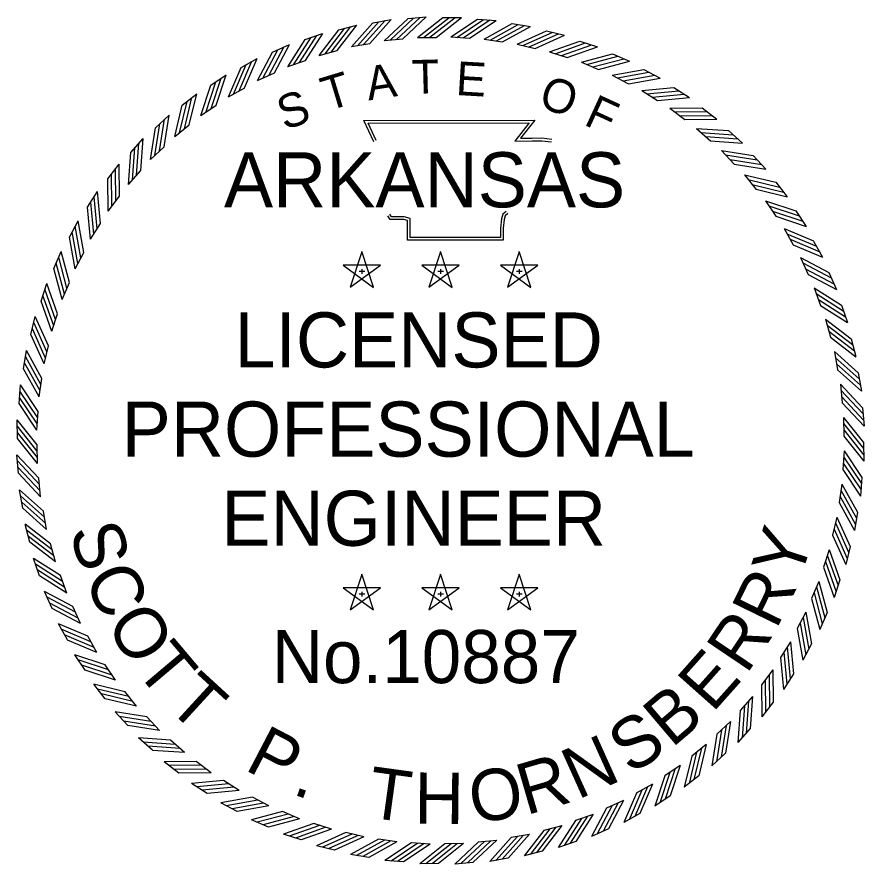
# Model space of a CAD drawing. Extents: x 166 to 3426, y 71 to 2074.
# Drawn here: x 2971.7 to 3220.1, y 237.2 to 485.7 of the extents above; entities that cross this region are included whole.
import ezdxf

# ---------------------------------------------------------------- set-up
doc = ezdxf.new("R2010")
doc.units = 0
doc.layers.add('STAMP', color=7, linetype='Continuous')

msp = doc.modelspace()

# ---------------------------------------------------------------- linework, layer by layer
at = {"layer": 'STAMP'}
for p, q in [((3076.12, 483.94), (3081.47, 484.89)), ((3086.3, 485.16), (3091.72, 485.66)), ((3096.6, 485.46), (3102.04, 485.46)), ((3106.79, 485.05), (3112.22, 484.65)), ((3066.07, 481.89), (3071.33, 483.27)), ((3116.96, 483.73), (3122.34, 482.89)), ((3056.22, 479.01), (3061.35, 480.82)), ((3089.18, 479.67), (3094.63, 479.67)), ((3098.96, 479.82), (3104.4, 479.42)), ((3126.99, 481.58), (3132.28, 480.29)), ((3046.65, 475.33), (3051.61, 477.56)), ((3069.81, 476.95), (3075.18, 477.9)), ((3079.44, 478.71), (3084.87, 479.21)), ((3108.73, 479.17), (3114.12, 478.32)), ((3118.41, 477.71), (3123.71, 476.42)), ((3136.81, 478.6), (3141.97, 476.88)), ((3060.36, 474.4), (3065.63, 475.79)), ((3127.93, 475.45), (3133.11, 473.73)), ((3146.34, 474.82), (3151.34, 472.68)), ((3037.41, 470.87), (3042.17, 473.51)), ((3051.15, 471.08), (3056.29, 472.89)), ((3137.24, 472.42), (3142.25, 470.27)), ((3155.53, 470.27), (3160.34, 467.73)), ((3028.58, 465.67), (3033.1, 468.69)), ((3042.25, 467.01), (3047.23, 469.24)), ((3146.26, 468.63), (3151.08, 466.08)), ((3033.72, 462.21), (3038.49, 464.85)), ((3164.31, 464.98), (3168.9, 462.04)), ((3020.2, 459.75), (3024.46, 463.13)), ((3154.94, 464.1), (3159.53, 461.16)), ((3025.61, 456.73), (3030.15, 459.76)), ((3163.22, 458.88), (3167.55, 455.57)), ((3172.63, 458.97), (3176.95, 455.67)), ((3012.34, 453.16), (3016.31, 456.89)), ((3017.98, 450.6), (3022.25, 453.99)), ((3171.03, 452.99), (3175.08, 449.33)), ((3180.42, 452.31), (3184.46, 448.66)), ((3005.05, 445.95), (3008.7, 449.99)), ((3010.88, 443.86), (3014.86, 447.59)), ((3178.34, 446.47), (3182.07, 442.49)), ((3187.64, 445.02), (3191.36, 441.05)), ((2998.38, 438.16), (3001.68, 442.48)), ((3004.37, 436.56), (3008.02, 440.6)), ((3185.08, 439.38), (3188.47, 435.1)), ((3194.23, 437.16), (3197.61, 432.89)), ((2992.38, 429.84), (2995.31, 434.42)), ((2998.48, 428.74), (3001.79, 433.08)), ((3191.21, 431.75), (3194.23, 427.21)), ((3200.14, 428.78), (3203.16, 424.25)), ((2987.08, 421.06), (2989.63, 425.87)), ((2993.25, 420.47), (2996.19, 425.06)), ((3196.69, 423.64), (3199.33, 418.87)), ((3205.35, 419.94), (3207.98, 415.18)), ((2982.53, 411.87), (2984.67, 416.87)), ((2988.73, 411.79), (2991.28, 416.61)), ((3072.83, 416.81), (3069.42, 406.37)), ((3076.22, 406.38), (3072.83, 416.83)), ((3095.9, 416.81), (3092.5, 406.37)), ((3099.3, 406.38), (3095.91, 416.83)), ((3118.98, 416.81), (3115.58, 406.37)), ((3122.37, 406.38), (3118.99, 416.83)), ((3201.48, 415.1), (3203.72, 410.13)), ((3078.31, 412.83), (3067.33, 412.84)), ((3067.34, 412.83), (3076.22, 406.36)), ((3069.44, 406.38), (3078.33, 412.82)), ((3101.39, 412.83), (3090.41, 412.84)), ((3090.42, 412.83), (3099.3, 406.36)), ((3092.51, 406.38), (3101.41, 412.82)), ((3124.47, 412.83), (3113.49, 412.84)), ((3113.5, 412.83), (3122.38, 406.36)), ((3115.59, 406.38), (3124.48, 412.82)), ((3072.04, 411.07), (3073.68, 411.07)), ((3072.84, 411.66), (3072.84, 410.28)), ((3095.12, 411.07), (3096.76, 411.07)), ((3095.92, 411.66), (3095.92, 410.28)), ((3118.2, 411.07), (3119.83, 411.07)), ((3118.99, 411.66), (3118.99, 410.28)), ((3209.81, 410.71), (3212.04, 405.74)), ((2978.76, 402.33), (2980.48, 407.49)), ((2984.94, 402.76), (2987.08, 407.78)), ((3205.55, 406.2), (3207.37, 401.06)), ((3213.48, 401.13), (3215.3, 396)), ((2975.78, 392.52), (2977.07, 397.8)), ((2981.9, 393.46), (2983.63, 398.63)), ((3208.87, 397), (3210.26, 391.72)), ((3216.36, 391.29), (3217.75, 386.03)), ((2973.62, 382.49), (2974.47, 387.86)), ((2979.65, 383.93), (2980.94, 389.23)), ((3211.42, 387.55), (3212.37, 382.18)), ((3218.41, 381.24), (3219.36, 375.88)), ((2972.3, 372.32), (2972.7, 377.74)), ((2978.19, 374.25), (2979.04, 379.64)), ((3213.18, 377.92), (3213.68, 372.49)), ((3219.63, 371.06), (3220.13, 365.64)), ((2977.53, 364.49), (2977.93, 369.93)), ((3214.14, 368.18), (3214.2, 362.73)), ((2971.83, 362.07), (2971.78, 367.51)), ((3220, 360.81), (3220.05, 355.37)), ((2977.69, 354.7), (2977.64, 360.16)), ((3214.3, 358.39), (3213.9, 352.95)), ((2972.2, 351.82), (2971.7, 357.24)), ((2978.65, 344.96), (2978.15, 350.39)), ((3219.53, 350.56), (3219.13, 345.14)), ((3213.64, 348.63), (3212.79, 343.24)), ((2973.42, 341.64), (2972.47, 347)), ((2980.41, 335.33), (2979.46, 340.71)), ((3218.21, 340.39), (3217.36, 335.02)), ((3212.18, 338.95), (3210.89, 333.65)), ((2975.47, 331.59), (2974.09, 336.85)), ((2982.96, 325.89), (2981.57, 331.16)), ((3209.93, 329.42), (3208.2, 324.25)), ((3216.05, 330.37), (3214.76, 325.08)), ((2978.35, 321.75), (2976.53, 326.88)), ((2986.28, 316.68), (2984.46, 321.82)), ((3072.83, 322.19), (3069.42, 311.75)), ((3076.22, 311.75), (3072.83, 322.2)), ((3095.9, 322.19), (3092.5, 311.75)), ((3099.3, 311.75), (3095.91, 322.2)), ((3118.98, 322.19), (3115.58, 311.75)), ((3122.37, 311.75), (3118.99, 322.2)), ((3213.07, 320.55), (3211.35, 315.39)), ((3078.31, 318.2), (3067.33, 318.21)), ((3067.34, 318.2), (3076.22, 311.74)), ((3069.44, 311.75), (3078.33, 318.2)), ((3101.39, 318.2), (3090.41, 318.21)), ((3090.42, 318.2), (3099.3, 311.74)), ((3092.51, 311.75), (3101.41, 318.2)), ((3124.47, 318.2), (3113.49, 318.21)), ((3113.5, 318.2), (3122.38, 311.74)), ((3115.59, 311.75), (3124.48, 318.2)), ((3206.89, 320.12), (3204.75, 315.1)), ((2982.02, 312.18), (2979.79, 317.14)), ((3072.04, 316.45), (3073.68, 316.45)), ((3072.84, 317.03), (3072.84, 315.66)), ((3095.12, 316.45), (3096.76, 316.45)), ((3095.92, 317.03), (3095.92, 315.66)), ((3118.2, 316.45), (3119.83, 316.45)), ((3118.99, 317.03), (3118.99, 315.66)), ((2990.35, 307.78), (2988.11, 312.75)), ((3203.1, 311.1), (3200.55, 306.28)), ((3209.3, 311.02), (3207.16, 306.01)), ((2986.48, 302.94), (2983.85, 307.7)), ((2995.14, 299.24), (2992.5, 304.02)), ((3198.58, 302.42), (3195.64, 297.82)), ((3204.75, 301.82), (3202.2, 297.02)), ((2991.69, 294.1), (2988.67, 298.63)), ((3000.62, 291.13), (2997.6, 295.67)), ((3193.35, 294.14), (3190.04, 289.81)), ((3199.45, 293.04), (3196.52, 288.46)), ((2997.6, 285.72), (2994.22, 289.99)), ((3006.75, 283.51), (3003.36, 287.78)), ((3187.46, 286.32), (3183.81, 282.28)), ((3193.45, 284.73), (3190.15, 280.4)), ((3004.19, 277.86), (3000.47, 281.83)), ((3013.49, 276.41), (3009.76, 280.39)), ((3180.95, 279.02), (3176.97, 275.29)), ((3186.78, 276.93), (3183.13, 272.9)), ((3011.41, 270.58), (3007.37, 274.22)), ((3020.8, 269.89), (3016.75, 273.55)), ((3173.85, 272.28), (3169.58, 268.89)), ((3179.49, 269.72), (3175.52, 266)), ((3019.2, 263.91), (3014.88, 267.21)), ((3028.61, 264), (3024.28, 267.31)), ((3166.22, 266.15), (3161.68, 263.12)), ((3036.89, 258.78), (3032.3, 261.72)), ((3171.63, 263.13), (3167.37, 259.75)), ((3027.52, 257.91), (3022.93, 260.84)), ((3158.11, 260.67), (3153.34, 258.03)), ((3045.57, 254.25), (3040.75, 256.81)), ((3163.25, 257.21), (3158.73, 254.2)), ((3036.3, 252.61), (3031.49, 255.16)), ((3149.58, 255.88), (3144.6, 253.64)), ((3054.59, 250.46), (3049.58, 252.61)), ((3140.68, 251.8), (3135.54, 249.99)), ((3154.42, 252.01), (3149.66, 249.37)), ((3045.49, 248.06), (3040.49, 250.2)), ((3063.9, 247.43), (3058.72, 249.15)), ((3131.47, 248.48), (3126.2, 247.1)), ((3055.03, 244.28), (3049.86, 246)), ((3073.42, 245.17), (3068.12, 246.46)), ((3145.18, 247.55), (3140.22, 245.32)), ((3083.1, 243.71), (3077.71, 244.56)), ((3112.39, 244.17), (3106.96, 243.67)), ((3122.02, 245.93), (3116.65, 244.99)), ((3135.61, 243.87), (3130.48, 242.06)), ((3064.84, 241.31), (3059.55, 242.59)), ((3092.87, 243.06), (3087.43, 243.46)), ((3102.65, 243.21), (3097.2, 243.16)), ((3125.76, 240.99), (3120.5, 239.61)), ((3074.87, 239.15), (3069.49, 240)), ((3115.71, 238.94), (3110.36, 238)), ((3085.04, 237.83), (3079.61, 238.23)), ((3095.28, 237.35), (3089.84, 237.3)), ((3105.53, 237.72), (3100.11, 237.23))]:
    msp.add_line(p, q, dxfattribs=at)
for points in [[(3073.38, 477.6), (3079.69, 484.59)], [(3075.17, 477.9), (3081.48, 484.89)], [(3079.43, 478.7), (3086.29, 485.15)], [(3081.18, 478.85), (3088.04, 485.3)], [(3083.05, 479.06), (3089.92, 485.51)], [(3084.86, 479.21), (3091.72, 485.66)], [(3089.17, 479.67), (3096.59, 485.46)], [(3090.92, 479.65), (3098.35, 485.44)], [(3092.81, 479.69), (3100.24, 485.48)], [(3094.62, 479.67), (3102.05, 485.46)], [(3098.96, 479.82), (3106.78, 485.05)], [(3100.7, 479.67), (3108.53, 484.9)], [(3102.59, 479.58), (3110.42, 484.81)], [(3104.4, 479.43), (3112.22, 484.66)], [(3062.05, 474.82), (3067.76, 482.31)], [(3063.87, 475.34), (3069.58, 482.83)], [(3065.63, 475.79), (3071.33, 483.28)], [(3069.8, 476.94), (3076.11, 483.93)], [(3071.53, 477.23), (3077.84, 484.22)], [(3108.72, 479.16), (3116.96, 483.73)], [(3110.45, 478.87), (3118.68, 483.44)], [(3112.32, 478.62), (3120.56, 483.19)], [(3114.11, 478.32), (3122.34, 482.89)], [(3052.8, 471.64), (3057.87, 479.57)], [(3054.57, 472.31), (3059.64, 480.24)], [(3056.29, 472.9), (3061.36, 480.83)], [(3060.35, 474.39), (3066.06, 481.88)], [(3118.4, 477.7), (3126.98, 481.57)], [(3120.1, 477.27), (3128.68, 481.14)], [(3121.94, 476.87), (3130.53, 480.74)], [(3123.7, 476.42), (3132.28, 480.29)], [(3047.22, 469.24), (3051.61, 477.57)], [(3051.15, 471.07), (3056.22, 479)], [(3127.92, 475.45), (3136.8, 478.6)], [(3129.58, 474.88), (3138.45, 478.03)], [(3131.39, 474.32), (3140.26, 477.47)], [(3042.25, 467), (3046.64, 475.32)], [(3043.85, 467.7), (3048.25, 476.03)], [(3045.56, 468.52), (3049.95, 476.84)], [(3133.1, 473.73), (3141.97, 476.88)], [(3137.23, 472.42), (3146.33, 474.82)], [(3036.89, 463.99), (3040.58, 472.65)], [(3038.48, 464.85), (3042.18, 473.51)], [(3138.83, 471.71), (3147.93, 474.12)], [(3140.59, 471.01), (3149.69, 473.41)], [(3142.25, 470.28), (3151.35, 472.68)], [(3033.71, 462.21), (3037.41, 470.87)], [(3035.25, 463.04), (3038.95, 471.7)], [(3146.25, 468.63), (3155.52, 470.27)], [(3028.62, 458.77), (3031.59, 467.7)], [(3030.14, 459.76), (3033.1, 468.69)], [(3147.79, 467.79), (3157.06, 469.44)], [(3149.48, 466.95), (3158.75, 468.59)], [(3151.08, 466.08), (3160.35, 467.73)], [(3025.61, 456.73), (3028.57, 465.66)], [(3027.07, 457.68), (3030.04, 466.62)], [(3154.93, 464.1), (3164.31, 464.98)], [(3022.24, 453.99), (3024.46, 463.14)], [(3156.4, 463.15), (3165.77, 464.02)], [(3158.01, 462.16), (3167.39, 463.03)], [(3017.98, 450.59), (3020.2, 459.74)], [(3019.36, 451.67), (3021.58, 460.82)], [(3020.81, 452.88), (3023.03, 462.03)], [(3159.53, 461.17), (3168.9, 462.04)], [(3163.21, 458.88), (3172.62, 458.98)], [(3164.59, 457.8), (3174, 457.9)], [(3013.52, 446.36), (3014.97, 455.66)], [(3014.85, 447.59), (3016.31, 456.89)], [(3076.33, 449.05), (3073.43, 455.33), (3123.61, 455.36), (3119.42, 450.09), (3122.83, 450.13), (3125.67, 450.17), (3128.52, 449.86)], [(3166.12, 456.69), (3175.53, 456.79)], [(3167.55, 455.58), (3176.96, 455.67)], [(3010.88, 443.85), (3012.34, 453.15)], [(3012.17, 445.04), (3013.62, 454.34)], [(3077.05, 449.38), (3074.67, 454.53), (3121.96, 454.56), (3117.75, 449.27), (3122.84, 449.34), (3125.64, 449.37), (3128.43, 449.07)], [(3171.02, 452.99), (3180.41, 452.31)], [(3008.02, 440.6), (3008.7, 449.99)], [(3172.31, 451.8), (3181.7, 451.12)], [(3173.74, 450.57), (3183.13, 449.89)], [(3005.55, 437.84), (3006.23, 447.23)], [(3006.79, 439.27), (3007.47, 448.66)], [(3175.08, 449.34), (3184.47, 448.66)], [(3004.37, 436.55), (3005.05, 445.94)], [(3178.33, 446.47), (3187.63, 445.02)], [(3179.51, 445.19), (3188.82, 443.73)], [(3001.78, 433.07), (3001.68, 442.49)], [(3180.84, 443.84), (3190.14, 442.38)], [(3182.06, 442.5), (3191.37, 441.05)], [(3000.67, 431.64), (3000.57, 441.06)], [(2998.48, 428.73), (2998.38, 438.15)], [(2999.55, 430.12), (2999.46, 439.53)], [(3185.07, 439.38), (3194.22, 437.16)], [(3186.14, 438), (3195.29, 435.78)], [(3187.35, 436.54), (3196.5, 434.32)], [(3188.46, 435.11), (3197.61, 432.89)], [(2995.19, 423.54), (2994.32, 432.91)], [(2996.19, 425.06), (2995.31, 434.43)], [(2993.25, 420.46), (2992.38, 429.83)], [(2994.21, 421.92), (2993.34, 431.3)], [(3191.2, 431.75), (3200.13, 428.78)], [(3192.16, 430.28), (3201.09, 427.32)], [(3115.7, 428.02), (3114.85, 427.32), (3114.56, 426.28), (3114.28, 423.68), (3114.28, 420.21), (3086.27, 420.21), (3086.27, 424.89), (3086.27, 425.93), (3085.13, 426.28), (3081.15, 426.28), (3080.44, 427.36)], [(3115.2, 428.63), (3114.15, 427.78), (3113.78, 426.43), (3113.48, 423.72), (3113.48, 421.01), (3087.06, 421.01), (3087.06, 424.89), (3087.06, 426.52), (3085.25, 427.08), (3081.58, 427.08), (3081.1, 427.8)], [(3193.24, 428.73), (3202.18, 425.77)], [(2991.27, 416.6), (2989.63, 425.87)], [(3194.23, 427.22), (3203.17, 424.25)], [(2989.56, 413.32), (2987.92, 422.59)], [(2990.41, 415.01), (2988.77, 424.28)], [(3196.68, 423.64), (3205.34, 419.95)], [(2988.73, 411.78), (2987.09, 421.05)], [(3197.51, 422.1), (3206.17, 418.41)], [(3198.47, 420.47), (3207.12, 416.77)], [(3199.33, 418.87), (3207.99, 415.18)], [(2986.35, 406.11), (2983.94, 415.21)], [(2987.08, 407.77), (2984.67, 416.87)], [(3201.47, 415.11), (3209.8, 410.71)], [(2985.64, 404.36), (2983.24, 413.46)], [(3202.18, 413.5), (3210.5, 409.11)], [(2984.94, 402.75), (2982.53, 411.86)], [(3202.99, 411.8), (3211.31, 407.4)], [(3203.72, 410.14), (3212.04, 405.74)], [(2983.62, 398.63), (2980.47, 407.5)], [(2983.03, 396.91), (2979.89, 405.78)], [(3205.54, 406.21), (3213.48, 401.14)], [(2982.47, 395.11), (2979.33, 403.98)], [(3206.11, 404.55), (3214.05, 399.48)], [(3206.78, 402.78), (3214.72, 397.71)], [(2981.91, 393.45), (2978.76, 402.32)], [(3207.37, 401.07), (3215.3, 396)], [(2980.93, 389.23), (2977.06, 397.81)], [(2980.49, 387.47), (2976.62, 396.05)], [(3208.87, 397), (3216.35, 391.29)], [(3209.3, 395.3), (3216.78, 389.6)], [(2980.08, 385.62), (2976.21, 394.21)], [(3209.82, 393.49), (3217.31, 387.78)], [(2979.65, 383.93), (2975.78, 392.51)], [(3210.26, 391.73), (3217.75, 386.02)], [(2979.03, 379.64), (2974.47, 387.87)], [(2978.73, 377.85), (2974.17, 386.08)], [(3211.42, 387.55), (3218.41, 381.25)], [(3211.71, 385.83), (3218.7, 379.52)], [(2978.48, 375.97), (2973.92, 384.21)], [(3212.07, 383.97), (3219.07, 377.67)], [(2978.19, 374.25), (2973.63, 382.48)], [(3212.37, 382.18), (3219.36, 375.88)], [(2977.93, 369.92), (2972.7, 377.75)], [(3213.18, 377.93), (3219.63, 371.06)], [(2977.78, 368.12), (2972.55, 375.94)], [(3213.32, 376.18), (3219.77, 369.32)], [(2977.68, 366.23), (2972.45, 374.06)], [(3213.54, 374.3), (3219.98, 367.44)], [(2977.54, 364.48), (2972.31, 372.31)], [(3213.69, 372.5), (3220.13, 365.63)], [(3214.14, 368.19), (3220, 360.82)], [(2977.63, 360.15), (2971.77, 367.52)], [(2977.63, 358.34), (2971.77, 365.71)], [(3214.14, 366.43), (3220, 359.06)], [(2977.69, 356.45), (2971.83, 363.82)], [(3214.2, 364.54), (3220.06, 357.17)], [(3214.2, 362.73), (3220.06, 355.36)], [(2977.69, 354.7), (2971.83, 362.07)], [(3214.29, 358.4), (3219.52, 350.57)], [(2978.14, 350.39), (2971.7, 357.25)], [(2978.29, 348.58), (2971.85, 355.44)], [(3214.15, 356.65), (3219.38, 348.83)], [(2978.51, 346.7), (2972.06, 353.56)], [(3213.9, 352.96), (3219.13, 345.13)], [(3214.05, 354.77), (3219.28, 346.94)], [(2978.65, 344.96), (2972.2, 351.82)], [(3213.64, 348.63), (3218.2, 340.4)], [(2979.46, 340.7), (2972.47, 347)], [(3213.35, 346.91), (3217.91, 338.67)], [(2979.76, 338.91), (2972.76, 345.22)], [(2980.12, 337.06), (2973.13, 343.36)], [(3212.8, 343.25), (3217.36, 335.01)], [(3213.1, 345.03), (3217.66, 336.8)], [(2980.41, 335.33), (2973.42, 341.63)], [(3212.18, 338.96), (3216.05, 330.37)], [(2981.57, 331.15), (2974.08, 336.86)], [(3211.34, 335.41), (3215.21, 326.83)], [(3211.75, 337.26), (3215.62, 328.68)], [(2982.01, 329.4), (2974.52, 335.1)], [(2982.53, 327.58), (2975.05, 333.28)], [(3210.9, 333.66), (3214.77, 325.07)], [(2982.96, 325.88), (2975.48, 331.59)], [(3209.92, 329.43), (3213.07, 320.56)], [(2984.46, 321.81), (2976.53, 326.88)], [(3208.8, 325.97), (3211.95, 317.1)], [(3209.36, 327.78), (3212.5, 318.9)], [(2985.05, 320.1), (2977.11, 325.17)], [(2985.72, 318.33), (2977.78, 323.4)], [(3208.21, 324.26), (3211.36, 315.38)], [(2986.29, 316.67), (2978.35, 321.74)], [(3206.19, 318.52), (3208.59, 309.42)], [(3206.89, 320.13), (3209.3, 311.02)], [(2988.11, 312.74), (2979.79, 317.14)], [(3205.48, 316.77), (3207.89, 307.67)], [(2988.84, 311.08), (2980.52, 315.48)], [(2989.65, 309.38), (2981.33, 313.77)], [(3204.75, 315.11), (3207.16, 306.01)], [(2990.36, 307.77), (2982.03, 312.17)], [(3203.1, 311.1), (3204.74, 301.83)], [(3202.27, 309.56), (3203.91, 300.29)], [(2992.5, 304.01), (2983.84, 307.7)], [(2993.36, 302.41), (2984.71, 306.11)], [(3200.56, 306.28), (3202.2, 297.01)], [(3201.42, 307.87), (3203.06, 298.6)], [(2994.32, 300.78), (2985.66, 304.47)], [(2995.15, 299.24), (2986.49, 302.93)], [(3197.62, 300.96), (3198.49, 291.58)], [(3198.58, 302.42), (3199.45, 293.05)], [(2997.6, 295.66), (2988.66, 298.63)], [(3196.64, 299.34), (3197.51, 289.97)], [(2998.59, 294.15), (2989.65, 297.11)], [(3195.64, 297.83), (3196.52, 288.45)], [(2999.67, 292.6), (2990.74, 295.56)], [(3000.63, 291.13), (2991.7, 294.1)], [(3193.35, 294.15), (3193.45, 284.73)], [(3191.16, 291.24), (3191.26, 281.82)], [(3192.28, 292.77), (3192.37, 283.35)], [(3003.37, 287.77), (2994.22, 289.99)], [(3004.48, 286.34), (2995.33, 288.56)], [(3190.05, 289.81), (3190.15, 280.39)], [(3005.69, 284.89), (2996.54, 287.1)], [(3006.76, 283.5), (2997.61, 285.72)], [(3187.46, 286.33), (3186.78, 276.94)], [(3185.04, 283.61), (3184.36, 274.22)], [(3186.28, 285.04), (3185.6, 275.65)], [(3009.77, 280.38), (3000.46, 281.83)], [(3183.81, 282.28), (3183.13, 272.89)], [(3010.99, 279.05), (3001.69, 280.5)], [(3012.32, 277.7), (3003.02, 279.15)], [(3180.95, 279.03), (3179.49, 269.73)], [(3013.5, 276.41), (3004.2, 277.86)], [(3178.31, 276.52), (3176.86, 267.22)], [(3179.66, 277.84), (3178.21, 268.54)], [(3016.75, 273.54), (3007.36, 274.22)], [(3176.98, 275.29), (3175.52, 265.99)], [(3018.09, 272.31), (3008.7, 273)], [(3019.52, 271.08), (3010.13, 271.76)], [(3172.47, 271.21), (3170.25, 262.06)], [(3173.85, 272.29), (3171.63, 263.14)], [(3020.81, 269.89), (3011.42, 270.57)], [(3169.59, 268.89), (3167.37, 259.74)], [(3171.02, 270), (3168.8, 260.86)], [(3024.28, 267.31), (3014.87, 267.21)], [(3025.71, 266.19), (3016.3, 266.1)], [(3166.22, 266.16), (3163.26, 257.22)], [(3027.24, 265.08), (3017.83, 264.98)], [(3028.62, 264), (3019.21, 263.91)], [(3163.21, 264.12), (3160.24, 255.18)], [(3164.76, 265.2), (3161.79, 256.26)], [(3032.3, 261.71), (3022.93, 260.84)], [(3161.69, 263.12), (3158.73, 254.19)], [(3033.82, 260.72), (3024.44, 259.85)], [(3035.43, 259.74), (3026.06, 258.86)], [(3036.9, 258.78), (3027.52, 257.91)], [(3154.94, 258.89), (3151.25, 250.23)], [(3156.58, 259.84), (3152.88, 251.18)], [(3158.12, 260.68), (3154.42, 252.02)], [(3040.75, 256.8), (3031.48, 255.15)], [(3042.35, 255.94), (3033.08, 254.29)], [(3153.35, 258.03), (3149.65, 249.37)], [(3044.04, 255.09), (3034.77, 253.44)], [(3045.58, 254.26), (3036.31, 252.61)], [(3144.61, 253.64), (3140.22, 245.31)], [(3146.27, 254.37), (3141.88, 246.04)], [(3147.98, 255.18), (3143.58, 246.85)], [(3149.58, 255.88), (3145.19, 247.56)], [(3049.58, 252.6), (3040.48, 250.2)], [(3051.24, 251.87), (3042.14, 249.47)], [(3053, 251.17), (3043.9, 248.76)], [(3139.03, 251.24), (3133.96, 243.31)], [(3140.68, 251.81), (3135.61, 243.88)], [(3054.6, 250.46), (3045.5, 248.06)], [(3058.73, 249.15), (3049.86, 246)], [(3060.44, 248.56), (3051.57, 245.41)], [(3131.48, 248.49), (3125.77, 241)], [(3135.54, 249.99), (3130.47, 242.05)], [(3137.26, 250.57), (3132.19, 242.64)], [(3062.25, 248), (3053.38, 244.85)], [(3063.91, 247.43), (3055.03, 244.28)], [(3068.13, 246.46), (3059.55, 242.59)], [(3069.89, 246.01), (3061.3, 242.15)], [(3126.2, 247.09), (3120.5, 239.61)], [(3127.96, 247.54), (3122.25, 240.05)], [(3129.78, 248.06), (3124.07, 240.57)], [(3071.73, 245.61), (3063.15, 241.74)], [(3073.43, 245.18), (3064.85, 241.31)], [(3077.72, 244.56), (3069.49, 239.99)], [(3079.51, 244.26), (3071.27, 239.69)], [(3081.38, 244.01), (3073.15, 239.44)], [(3083.11, 243.72), (3074.87, 239.15)], [(3106.97, 243.67), (3100.11, 237.22)], [(3108.78, 243.82), (3101.92, 237.37)], [(3110.65, 244.03), (3103.79, 237.59)], [(3112.4, 244.18), (3105.54, 237.73)], [(3116.66, 244.98), (3110.35, 237.99)], [(3118.45, 245.28), (3112.14, 238.29)], [(3120.3, 245.65), (3113.99, 238.66)], [(3122.03, 245.94), (3115.72, 238.95)], [(3087.43, 243.45), (3079.61, 238.23)], [(3089.24, 243.3), (3081.41, 238.08)], [(3091.13, 243.21), (3083.3, 237.98)], [(3092.87, 243.06), (3085.05, 237.83)], [(3097.21, 243.16), (3089.84, 237.3)], [(3099.02, 243.16), (3091.65, 237.3)], [(3100.91, 243.22), (3093.54, 237.36)], [(3102.66, 243.22), (3095.29, 237.36)]]:
    msp.add_lwpolyline(points, dxfattribs=at)

# ---------------------------------------------------------------- texts
for s, height, rotation, p in [('T', 9.9, 1.4789, (3087.58, 463.1)), ('E', 9.9, 356.672, (3100.25, 462.79)), ('T', 9.9, 16.9015, (3062.78, 457.99)), ('A', 9.9, 8.6788, (3074.8, 461.13)), ('O', 9.9, 341.2218, (3124.28, 459.4)), ('S', 9.9, 19.7726, (3050.2, 452.34)), ('F', 9.9, 335.3628, (3137.62, 454.18)), ('S', 15.03, 287.2223, (2986.93, 334.97)), ('Y', 15.03, 72.0481, (3201.2, 319.96)), ('C', 15.03, 294.5183, (2991.18, 321.28)), ('R', 15.03, 64.0225, (3194.38, 305.74)), ('O', 15.03, 302.1791, (2997.47, 307.61)), ('R', 15.03, 55.9969, (3185.65, 292.61)), ('T', 15.03, 310.2047, (3005.95, 294.31)), ('E', 15.03, 48.3361, (3175.68, 281.34)), ('T', 15.03, 317.5007, (3015.21, 283.37)), ('B', 15.03, 40.3105, (3163.72, 271.06)), ('S', 15.03, 33.0144, (3151.7, 263.25)), ('P', 15.03, 332.4576, (3038.11, 265.04)), ('N', 15.03, 24.2592, (3136.11, 255.98)), ('R', 15.03, 16.2336, (3121, 251.47)), ('T', 15.03, 352.1568, (3074.01, 251.02)), ('H', 15.03, 359.4528, (3088.21, 249.07)), ('O', 15.03, 8.208, (3105.41, 249.12)), ('.', 15.03, 340.4832, (3052.13, 257.84))]:
    msp.add_text(s, height=height, rotation=rotation, dxfattribs=at).set_placement(p)
for s, height, p in [('ARKANSAS', 16.155, (3032.41, 429.82)), ('LICENSED', 16.155, (3035.49, 382.87)), ('PROFESSIONAL', 16.1547, (3002.41, 356.71)), ('ENGINEER', 16.155, (3031.64, 330.56)), ('No.10887', 15.578, (3046.41, 290.28))]:
    msp.add_text(s, height=height, dxfattribs=at).set_placement(p)

doc.saveas('drawing.dxf')
